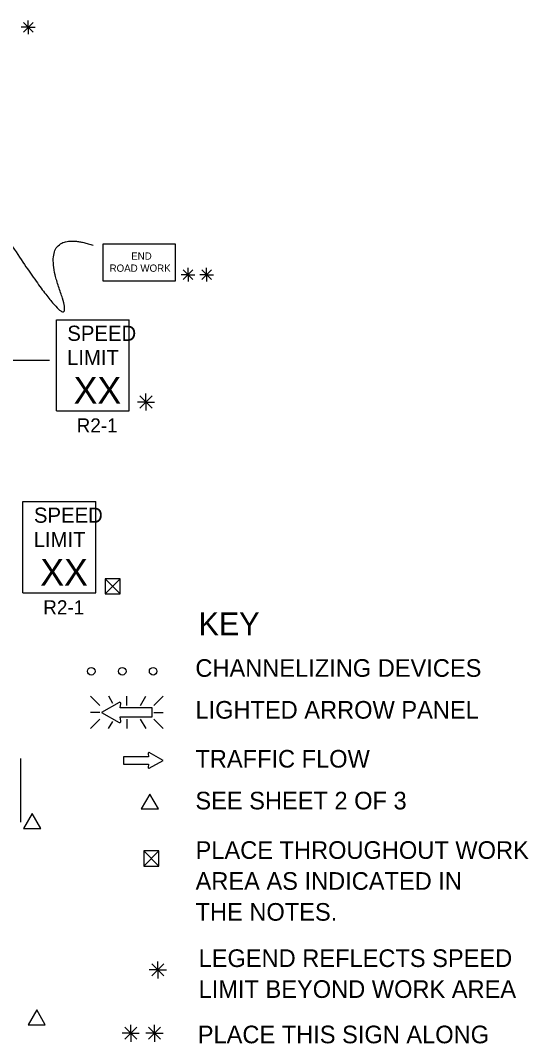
# Model space of a CAD drawing. Extents: x 16630 to 19509, y 5576 to 6998.
# Drawn here: x 17161 to 17428, y 6304 to 6844 of the extents above; entities that cross this region are included whole.
import ezdxf

# ---------------------------------------------------------------- set-up
doc = ezdxf.new("R2010")
doc.units = 0
for name, color, linetype in [('MT_SCRATCH_LEVEL_E', 7, 'Continuous'), ('TRAFFIC_SIGNS_PR', 7, 'Continuous'), ('TYPICAL_TEXT_DIMEN_EX', 7, 'Continuous'), ('TYPICAL_TEXT_DIMEN_PR', 7, 'Continuous')]:
    doc.layers.add(name, color=color, linetype=linetype)

msp = doc.modelspace()

# ---------------------------------------------------------------- linework, layer by layer
at = {"layer": 'MT_SCRATCH_LEVEL_E'}
for p, q in [((17227.72, 6457.25), (17228.03, 6455.48)), ((17235.64, 6453.62), (17228.4, 6457.73)), ((17228.03, 6455.48), (17214.78, 6455.48)), ((17214.78, 6455.48), (17214.78, 6451.73)), ((17214.78, 6451.73), (17228.03, 6451.73)), ((17228.03, 6451.73), (17227.72, 6449.95)), ((17228.4, 6449.48), (17235.64, 6453.62))]:
    msp.add_line(p, q, dxfattribs=at)
for centre, start, end in [((17228.18, 6457.33), 60.4248, 189.9638), ((17228.18, 6449.89), 170.0362, 299.7731)]:
    msp.add_arc(centre, 0.463, start, end, dxfattribs=at)
at = {"layer": 'TRAFFIC_SIGNS_PR'}
for p, q in [((17179.45, 6685.93), (17217.85, 6685.93)), ((17179.45, 6637.93), (17179.45, 6685.93)), ((17217.85, 6637.93), (17217.85, 6685.93)), ((17179.45, 6637.93), (17217.85, 6637.93)), ((17161.88, 6590.04), (17200.28, 6590.04)), ((17161.88, 6542.04), (17161.88, 6590.04)), ((17200.28, 6542.04), (17200.28, 6590.04)), ((17161.88, 6542.04), (17200.28, 6542.04)), ((17197.49, 6487.43), (17202.43, 6482.5)), ((17209.26, 6483.61), (17207.05, 6487.44)), ((17216.58, 6482.5), (17216.58, 6487.44)), ((17223.81, 6482.5), (17226.66, 6487.44)), ((17230.72, 6482.5), (17235.66, 6487.44)), ((17202.43, 6478.94), (17197.49, 6478.94)), ((17230.72, 6478.94), (17235.66, 6478.94)), ((17197.49, 6470.46), (17202.43, 6475.39)), ((17207, 6470.45), (17209.12, 6474.12)), ((17216.58, 6475.39), (17216.58, 6470.45)), ((17226.7, 6470.45), (17223.85, 6475.39)), ((17230.72, 6475.39), (17235.66, 6470.45)), ((17160.55, 6454.67), (17160.55, 6421.07))]:
    msp.add_line(p, q, dxfattribs=at)
msp.add_lwpolyline([(17203.87, 6706.48), (17242.27, 6706.48), (17242.27, 6725.68), (17203.87, 6725.68)], close=True, dxfattribs=at)
for points in [[(17212.5, 6484.22), (17203.21, 6478.94), (17212.51, 6473.62)], [(17213.38, 6474.25), (17212.98, 6476.52), (17229.99, 6476.52), (17229.99, 6481.32), (17212.98, 6481.32), (17213.38, 6483.6)]]:
    msp.add_lwpolyline(points, dxfattribs=at)
for centre in [(17197.83, 6500.63), (17214.13, 6500.63), (17230.43, 6500.63)]:
    msp.add_circle(centre, 2, dxfattribs=at)
for centre, radius, start, end in [((17212.79, 6483.7), 0.598, 350.7308, 118.8916), ((17212.79, 6474.15), 0.597, 241.4833, 9.9593)]:
    msp.add_arc(centre, radius, start, end, dxfattribs=at)
at = {"layer": 'TYPICAL_TEXT_DIMEN_PR'}
for p, q in [((17164.62, 6840.13), (17161, 6840.13)), ((17167.17, 6842.68), (17162.07, 6837.58)), ((17162.08, 6842.68), (17167.17, 6837.58)), ((17164.62, 6840.13), (17164.62, 6843.69)), ((17164.62, 6840.13), (17167.17, 6840.13)), ((17164.62, 6840.13), (17168.21, 6840.13)), ((17164.62, 6840.13), (17164.62, 6836.53)), ((17248.82, 6709.68), (17245.19, 6709.68)), ((17246.27, 6712.23), (17251.37, 6707.13)), ((17251.37, 6712.23), (17246.27, 6707.13)), ((17248.82, 6709.68), (17248.82, 6713.25)), ((17248.82, 6709.68), (17251.37, 6709.68)), ((17248.82, 6709.68), (17252.4, 6709.68)), ((17248.82, 6709.68), (17248.82, 6706.08)), ((17258.57, 6709.68), (17254.94, 6709.68)), ((17261.12, 6712.23), (17256.01, 6707.13)), ((17256.02, 6712.23), (17261.12, 6707.13)), ((17258.57, 6709.68), (17258.57, 6713.25)), ((17258.57, 6709.68), (17261.12, 6709.68)), ((17258.57, 6709.68), (17262.15, 6709.68)), ((17258.57, 6709.68), (17258.57, 6706.08)), ((17142.7, 6664.64), (17175.9, 6664.64)), ((17142.7, 6664.64), (17175.9, 6664.64)), ((17142.7, 6664.64), (17175.9, 6664.64)), ((17223.45, 6645.73), (17229.83, 6639.36)), ((17229.83, 6645.73), (17223.45, 6639.36)), ((17226.64, 6642.55), (17226.64, 6647)), ((17226.64, 6642.55), (17222.11, 6642.55)), ((17226.64, 6642.55), (17229.83, 6642.55)), ((17226.64, 6642.55), (17231.12, 6642.55)), ((17226.64, 6642.55), (17226.64, 6638.05)), ((17205.07, 6549.36), (17213.07, 6541.36)), ((17205.07, 6541.36), (17213.07, 6549.36)), ((17225.49, 6405.9), (17233.49, 6397.9)), ((17225.49, 6397.9), (17233.49, 6405.9)), ((17232.92, 6343.19), (17228.38, 6343.19)), ((17229.73, 6346.37), (17236.1, 6340)), ((17236.1, 6346.37), (17229.73, 6340)), ((17232.92, 6343.19), (17232.92, 6347.64)), ((17232.92, 6343.19), (17236.1, 6343.19)), ((17232.92, 6343.19), (17237.39, 6343.19)), ((17232.92, 6343.19), (17232.92, 6338.69)), ((17215.44, 6313.03), (17221.81, 6306.66)), ((17221.81, 6313.03), (17215.44, 6306.66)), ((17218.63, 6309.85), (17218.63, 6314.3)), ((17234.37, 6313.03), (17227.99, 6306.66)), ((17228, 6313.03), (17234.37, 6306.66)), ((17231.18, 6309.85), (17231.18, 6314.3)), ((17218.63, 6309.85), (17214.1, 6309.85)), ((17218.63, 6309.85), (17221.81, 6309.85)), ((17218.63, 6309.85), (17223.1, 6309.85)), ((17218.63, 6309.85), (17218.63, 6305.35)), ((17231.18, 6309.85), (17226.65, 6309.85)), ((17231.18, 6309.85), (17234.37, 6309.85)), ((17231.18, 6309.85), (17235.66, 6309.85)), ((17231.18, 6309.85), (17231.18, 6305.35))]:
    msp.add_line(p, q, dxfattribs=at)
for points in [[(17205.07, 6549.36), (17205.07, 6541.36), (17213.07, 6541.36), (17213.07, 6549.36)], [(17228.71, 6435.91), (17224.18, 6428.08), (17233.23, 6428.08)], [(17166.67, 6425.66), (17162.15, 6417.82), (17171.2, 6417.82)], [(17225.49, 6405.9), (17225.49, 6397.9), (17233.49, 6397.9), (17233.49, 6405.9)], [(17169.08, 6322.07), (17164.56, 6314.24), (17173.61, 6314.24)]]:
    msp.add_lwpolyline(points, close=True, dxfattribs=at)
msp.add_open_spline([(17154.48, 6727.28), (17192.72, 6669.11), (17169.5, 6734.81), (17198.86, 6725.23)], degree=2, dxfattribs=at)

# ---------------------------------------------------------------- texts
at = {"layer": 'TRAFFIC_SIGNS_PR'}
for s, height, p in [('END', 3.831, (17218.87, 6717.6)), ('ROAD WORK', 3.831, (17207.48, 6711.22)), ('SPEED', 8, (17185.22, 6674.79)), ('LIMIT', 8, (17185.06, 6661.99)), ('XX', 14.031, (17188.56, 6641.69)), ('R2-1', 7.44, (17190.13, 6626.49)), ('SPEED', 8, (17167.64, 6578.9)), ('LIMIT', 8, (17167.48, 6566.1)), ('XX', 14.031, (17170.99, 6545.8)), ('R2-1', 7.44, (17172.55, 6530.6))]:
    msp.add_text(s, height=height, dxfattribs=at).set_placement(p)
at = {"layer": 'TYPICAL_TEXT_DIMEN_EX'}
for s, height, p in [('KEY', 12, (17254.34, 6519.6)), ('CHANNELIZING DEVICES', 9.3, (17252.68, 6497.69)), ('LIGHTED ARROW PANEL', 9.3, (17252.68, 6475.64)), ('TRAFFIC FLOW', 9.3, (17252.68, 6449.84)), ('SEE SHEET 2 OF 3', 9.3, (17252.68, 6427.79)), ('PLACE THROUGHOUT WORK', 9.3, (17252.78, 6401.72)), ('AREA AS INDICATED IN', 9.3, (17252.78, 6385.42)), ('THE NOTES.', 9.3, (17252.78, 6369.12)), ('LEGEND REFLECTS SPEED', 9.3, (17254.37, 6344.72)), ('LIMIT BEYOND WORK AREA', 9.3, (17254.37, 6328.42)), ('PLACE THIS SIGN ALONG', 9.3, (17253.92, 6304.51))]:
    msp.add_text(s, height=height, dxfattribs=at).set_placement(p)

doc.saveas('drawing.dxf')
